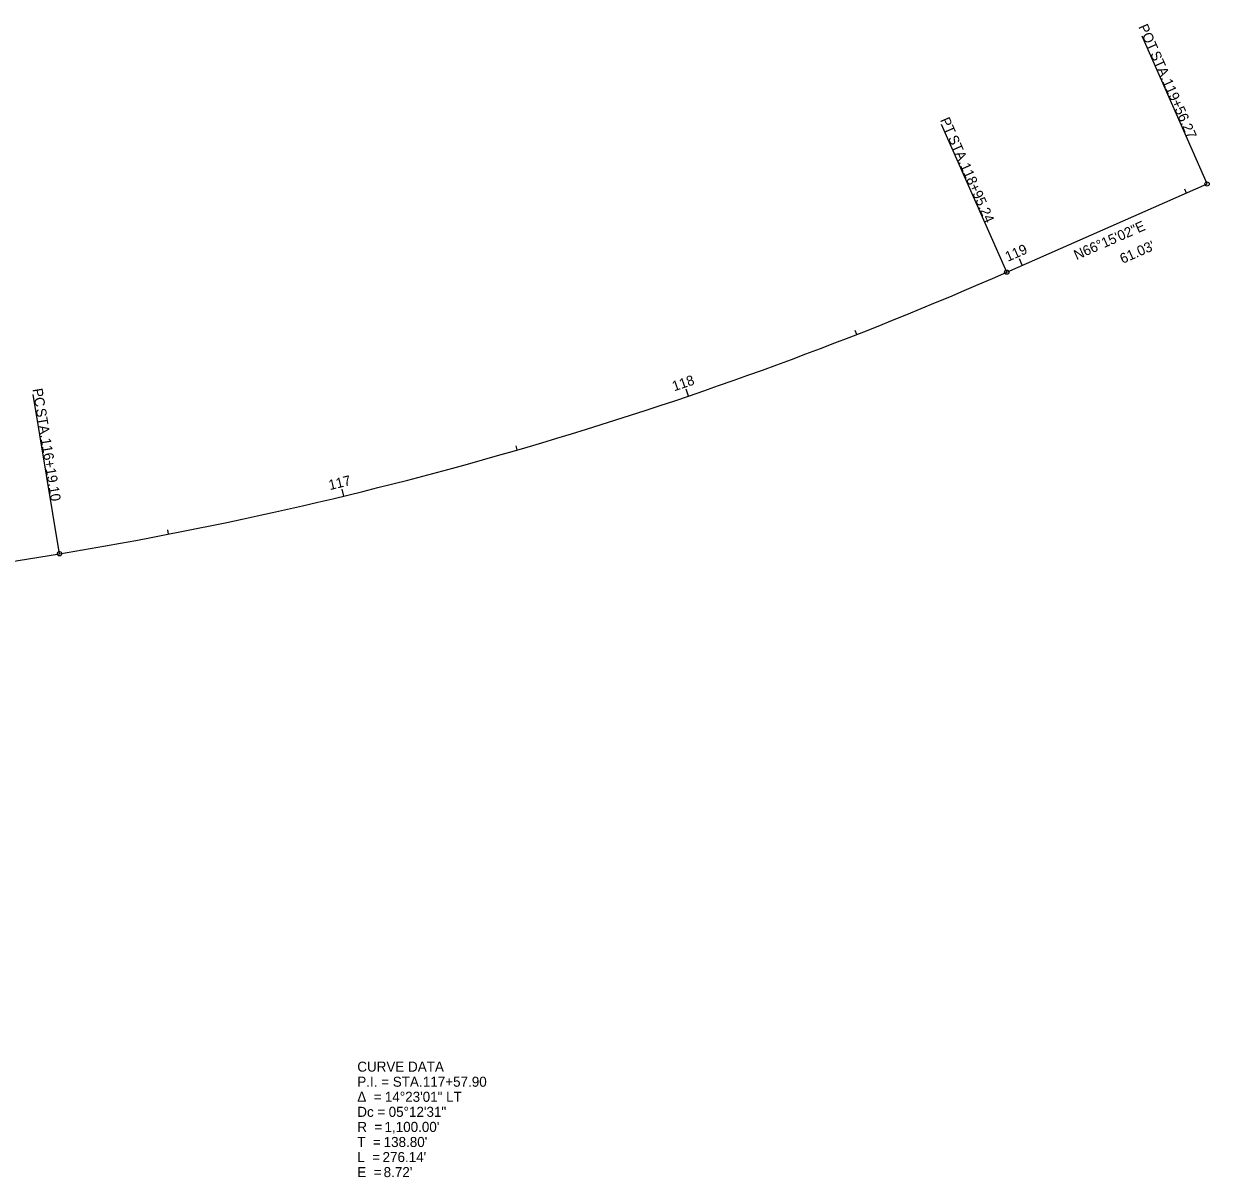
# Model space of a CAD drawing. Extents: x 1462082 to 1464344, y 432818 to 434093.
# Drawn here: x 1463678.5 to 1464009, y 433771.7 to 434093.3 of the extents above; entities that cross this region are included whole.
import ezdxf

# ---------------------------------------------------------------- set-up
doc = ezdxf.new("R2010")
doc.units = 0
for name, color, linetype in [('GE_P_Alignment', 7, 'Continuous'), ('GE_P_Alignment_100_Bearings', 7, 'Continuous'), ('GE_P_Alignment_100_Cardinal_Points', 7, 'Continuous'), ('GE_P_Alignment_100_Curve_Data', 7, 'Continuous'), ('GE_P_Alignment_100_Distances', 7, 'Continuous'), ('GE_P_Alignment_100_Stations', 7, 'Continuous')]:
    doc.layers.add(name, color=color, linetype=linetype)

msp = doc.modelspace()

# ---------------------------------------------------------------- linework, layer by layer
at = {"layer": 'GE_P_Alignment'}
for p, q in [((1463952.5, 434024), (1464008.36, 434048.58)), ((1463952.5, 434024), (1464008.36, 434048.58)), ((1463025.07, 433836.09), (1463688.5, 433945.51)), ((1463025.07, 433836.09), (1463688.5, 433945.51))]:
    msp.add_line(p, q, dxfattribs=at)
msp.add_arc((1463509.49, 435030.85), 1100, 279.36586, 293.74933, dxfattribs=at)
msp.add_arc((1463509.49, 435030.85), 1100, 279.36586, 293.74933, dxfattribs=at)
at = {"layer": 'GE_P_Alignment_100_Cardinal_Points'}
for p, q in [((1464008.36, 434048.58), (1463990.24, 434089.77)), ((1463952.5, 434024), (1463934.37, 434065.19)), ((1463688.5, 433945.51), (1463681.18, 433989.91))]:
    msp.add_line(p, q, dxfattribs=at)
for centre in [(1464008.36, 434048.58), (1463952.5, 434024), (1463688.5, 433945.51)]:
    msp.add_circle(centre, 0.6, dxfattribs=at)
at = {"layer": 'GE_P_Alignment_100_Stations'}
for p, q in [((1464002.62, 434046.06), (1464002.14, 434047.15)), ((1463956.85, 434025.92), (1463956.05, 434027.75)), ((1463910.73, 434006.64), (1463910.29, 434007.76)), ((1463863.77, 433989.46), (1463863.13, 433991.36)), ((1463816.09, 433974.44), (1463815.75, 433975.59)), ((1463767.77, 433961.6), (1463767.3, 433963.55)), ((1463718.92, 433950.97), (1463718.69, 433952.15))]:
    msp.add_line(p, q, dxfattribs=at)

# ---------------------------------------------------------------- texts
at = {"layer": 'GE_P_Alignment_100_Bearings'}
msp.add_text('N66°15\'02"E', height=2.8, rotation=23.7493, dxfattribs=at).set_placement((1463971.96, 434027.32))
at = {"layer": 'GE_P_Alignment_100_Cardinal_Points'}
for s, rotation, p in [('POT', 293.7493, (1463989.12, 434092.41)), (' STA. ', 293.7493, (1463992.02, 434085.82)), ('119+56.27', 293.7493, (1463995.83, 434077.17)), ('PT', 293.7493, (1463933.88, 434066.43)), (' STA. ', 293.7493, (1463935.65, 434062.38)), ('118+95.24', 293.7493, (1463939.46, 434053.73)), ('PC', 279.3659, (1463680.97, 433991.39)), (' STA. ', 279.3659, (1463681.72, 433986.87)), ('116+19.10', 279.3659, (1463683.26, 433977.54))]:
    msp.add_text(s, height=2.8, rotation=rotation, dxfattribs=at).set_placement(p)
at = {"layer": 'GE_P_Alignment_100_Curve_Data'}
for s, p in [('CURVE DATA', (1463771.5, 433801.13)), ('P.I. = STA. ', (1463771.5, 433796.93)), ('117+57.90', (1463789.77, 433796.93)), ('Δ  = ', (1463771.5, 433792.73)), ('14°23\'01" LT', (1463779.18, 433792.73)), ('Dc = ', (1463771.5, 433788.53)), ('05°12\'31"', (1463780.24, 433788.53)), ('R  = ', (1463771.5, 433784.33)), ("1,100.00'", (1463779.08, 433784.33)), ('T  = ', (1463771.5, 433780.13)), ("138.80'", (1463778.84, 433780.13)), ('L  = ', (1463771.5, 433775.93)), ("276.14'", (1463778.54, 433775.93)), ('E  = ', (1463771.5, 433771.73)), ("8.72'", (1463778.84, 433771.73))]:
    msp.add_text(s, height=2.8, dxfattribs=at).set_placement(p)
at = {"layer": 'GE_P_Alignment_100_Distances'}
msp.add_text("61.03'", height=2.8, rotation=23.7493, dxfattribs=at).set_placement((1463984.8, 434026.29))
at = {"layer": 'GE_P_Alignment_100_Stations'}
for s, rotation, p in [('119', 23.7493, (1463952.81, 434026.87)), ('118', 18.7886, (1463859.81, 433990.76)), ('117', 13.5799, (1463763.86, 433963.23))]:
    msp.add_text(s, height=2.8, rotation=rotation, dxfattribs=at).set_placement(p)

doc.saveas('drawing.dxf')
